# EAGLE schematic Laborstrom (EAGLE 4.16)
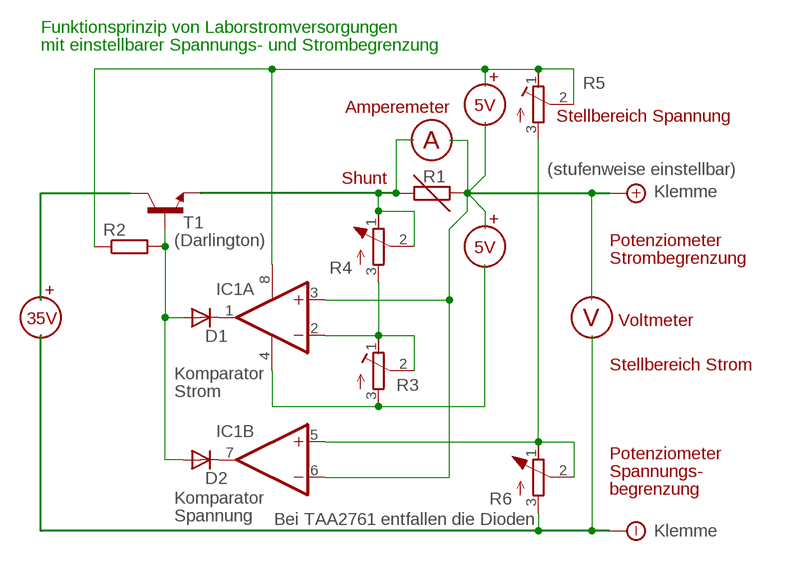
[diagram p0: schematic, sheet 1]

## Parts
D1  DIODE-D-10  [D-10]
D2  DIODE-D-10  [D-10]
IC1  TL082P  [DIL08]
R1  R-EU_0207/10  [0207/10]
R2  R-EU_0207/10  [0207/10]
R3  R-TRIMMT93YB  [RTRIMT93YB]
R4  R-TRIMMT93YB  [RTRIMT93YB]
R5  R-TRIMMT93YB  [RTRIMT93YB]
R6  R-TRIMMT93YB  [RTRIMT93YB]
T1  -NPN-TO3/  [TO3]

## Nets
00: IC1.3(A:+IN) IC1.6(B:-IN) R1.1 ; supply symbol labelled Klemme
5N: IC1.4(P:V-) R3.3(E)
5P: IC1.8(P:V+) R2.1 R5.1(A) R5.2(S)
+UB: T1.C
-UB: R6.3(E) ; supply symbol labelled Klemme
N$1: D1.A D2.A R2.2 T1.B
N$7: IC1.2(A:-IN) R3.1(A) R3.2(S) R4.3(E)
N$8: D2.C IC1.7(B:OUT)
N$9: D1.C IC1.1(A:OUT)
N$15: R1.2 R4.1(A) R4.2(S) T1.E
N$85: IC1.5(B:+IN) R5.3(E) R6.1(A) R6.2(S)

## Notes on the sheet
- Funktionsprinzip von Laborstromversorgungen
- mit einstellbarer Spannungs- und Strombegrenzung
- +
- Amperemeter | 5V
- Stellbereich Spannung
- A
- (stufenweise einstellbar)
- Shunt
- +
- (Darlington) | Potenziometer
- 5V
- Strombegrenzung
- +
- 35V | V | Voltmeter
- Stellbereich Strom
- Komparator
- Strom
- Potenziometer
- Spannungs-
- begrenzung
- Komparator
- Spannung | Bei TAA2761 entfallen die Dioden

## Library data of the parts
D1 D2 = diode:DIODE-: DIODE
IC1 = linear:TL082: OP AMP
R1 R2 = rcl:R-EU_: RESISTOR, European symbol
R3-R6 = rcl:R-TRIMM: Trimm resistor
T1 = transistor:*-NPN-: NPN Transistror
